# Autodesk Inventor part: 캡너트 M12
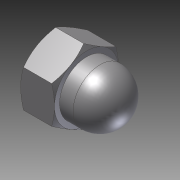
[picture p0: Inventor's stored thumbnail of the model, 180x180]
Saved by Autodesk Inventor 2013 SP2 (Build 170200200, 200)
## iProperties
Created: 2024-07
Part Number: 캡너트 M12
Material: Generic
Document SubType Name: Modeling
Designer: 601
Density: 1 g/cm^3
Author: 601
변환 표준: STEP AP214IS
전처리기: Build: 200, Release: 2013 SP2 Update 6 - Date: Thu 07/17/2014
전송 단위: 밀리미터
불확실성: 0.01
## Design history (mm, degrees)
node "캡너트 M121"
body "Solid1"
node "기준1"
